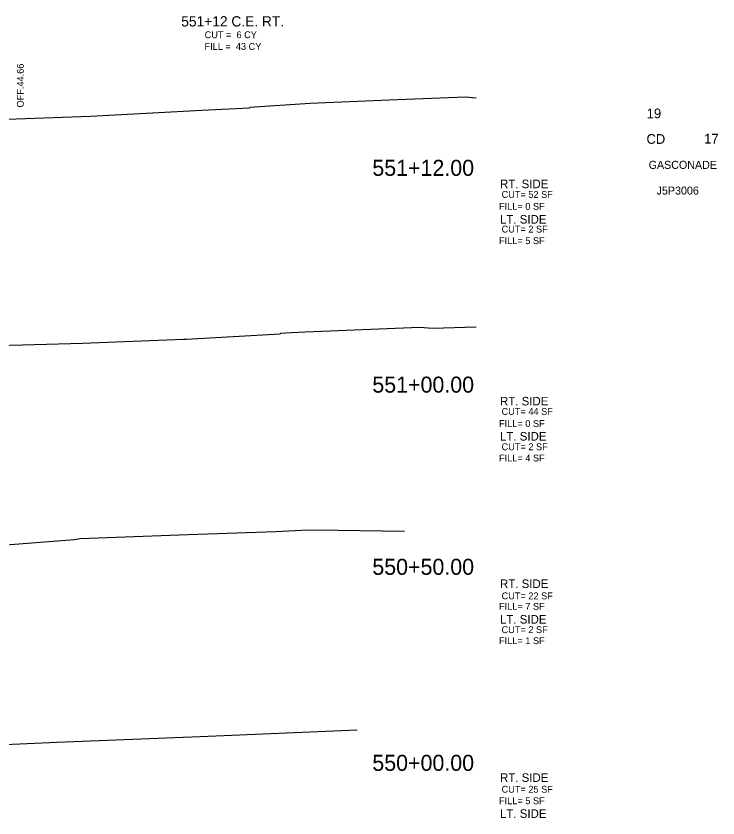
# Model space of a CAD drawing. Extents: x -4 to 359, y 0 to 1436.
# Drawn here: x 297.2 to 358.6, y 924 to 994.1 of the extents above; entities that cross this region are included whole.
import ezdxf

# ---------------------------------------------------------------- set-up
doc = ezdxf.new("R2010")
doc.units = 0
for name, color, linetype in [('Common-Title block info', 7, 'Continuous'), ('XS-Existing surface-ground', 7, 'Continuous'), ('XS-Text-earthwork labels', 7, 'Continuous'), ('XS-Text-offset label', 7, 'Continuous'), ('XS-Text-tie elevation', 7, 'Continuous')]:
    doc.layers.add(name, color=color, linetype=linetype)

msp = doc.modelspace()

# ---------------------------------------------------------------- linework, layer by layer
at = {"layer": 'XS-Existing surface-ground'}
for p, q in [((322.981, 986.503), (329.892, 986.795)), ((329.892, 986.795), (336.553, 987.062)), ((336.553, 987.062), (337.5, 986.997)), ((303.741, 985.392), (313.506, 985.892)), ((313.506, 985.892), (317.66, 986.121)), ((317.66, 986.121), (317.685, 986.159)), ((317.685, 986.159), (322.981, 986.503)), ((294.465, 985.036), (303.741, 985.392)), ((333.671, 966.846), (337.5, 966.957)), ((312.119, 965.88), (320.359, 966.334)), ((320.359, 966.334), (320.409, 966.409)), ((320.409, 966.409), (321.334, 966.469)), ((321.334, 966.469), (322.54, 966.52)), ((322.54, 966.52), (332.57, 966.922)), ((332.57, 966.922), (333.671, 966.846)), ((303.044, 965.529), (311.881, 965.868)), ((311.881, 965.868), (312.119, 965.88)), ((294.329, 965.286), (297.792, 965.395)), ((297.792, 965.395), (303.044, 965.529)), ((302.841, 948.449), (312.304, 948.81)), ((312.304, 948.81), (319.961, 949.055)), ((319.961, 949.055), (322.775, 949.213)), ((322.775, 949.213), (325.427, 949.18)), ((325.427, 949.18), (331.21, 949.102)), ((284.805, 947.033), (302.351, 948.364)), ((302.351, 948.364), (302.841, 948.449)), ((313.335, 931.153), (327.095, 931.723)), ((295.167, 930.401), (300.81, 930.64)), ((300.81, 930.64), (313.335, 931.153))]:
    msp.add_line(p, q, dxfattribs=at)

# ---------------------------------------------------------------- texts
at = {"layer": 'Common-Title block info'}
for s, height, p in [('19', 0.85, (352.417, 985.199)), ('CD', 0.85, (352.395, 982.961)), ('17', 0.85, (357.442, 982.988)), ('GASCONADE', 0.7, (352.581, 980.774)), ('J5P3006', 0.7, (353.279, 978.524))]:
    msp.add_text(s, height=height, dxfattribs=at).set_placement(p)
at = {"layer": 'XS-Text-earthwork labels'}
for s, height, p in [('551+12 C.E. RT.', 0.9, (311.692, 993.222)), ('CUT =  6 CY           ', 0.6, (313.739, 992.199)), ('FILL =  43 CY           ', 0.6, (313.729, 991.178)), ('RT. SIDE', 0.75, (339.577, 979.083)), (' CUT= 52 SF           ', 0.6, (339.495, 978.235)), ('FILL= 0 SF           ', 0.6, (339.495, 977.191)), ('LT. SIDE', 0.75, (339.577, 975.987)), (' CUT= 2 SF           ', 0.6, (339.495, 975.205)), ('FILL= 5 SF           ', 0.6, (339.495, 974.192)), ('RT. SIDE', 0.75, (339.577, 960.088)), (' CUT= 44 SF           ', 0.6, (339.495, 959.262)), ('FILL= 0 SF           ', 0.6, (339.495, 958.203)), ('LT. SIDE', 0.75, (339.577, 957.012)), (' CUT= 2 SF           ', 0.6, (339.495, 956.171)), ('FILL= 4 SF           ', 0.6, (339.495, 955.188)), ('RT. SIDE', 0.75, (339.577, 944.123)), (' CUT= 22 SF           ', 0.6, (339.495, 943.135)), ('FILL= 7 SF           ', 0.6, (339.495, 942.215)), ('LT. SIDE', 0.75, (339.577, 941.011)), (' CUT= 2 SF           ', 0.6, (339.495, 940.181)), ('FILL= 1 SF           ', 0.6, (339.495, 939.216)), ('RT. SIDE', 0.75, (339.577, 927.169)), (' CUT= 25 SF           ', 0.6, (339.495, 926.225)), ('FILL= 5 SF           ', 0.6, (339.495, 925.22)), ('LT. SIDE', 0.75, (339.577, 924.026))]:
    msp.add_text(s, height=height, dxfattribs=at).set_placement(p)
at = {"layer": 'XS-Text-offset label'}
for s, p in [('           551+12.00           ', (322.687, 980.163)), ('           551+00.00           ', (322.687, 961.205)), ('           550+50.00           ', (322.687, 945.277)), ('           550+00.00           ', (322.687, 928.137))]:
    msp.add_text(s, height=1.4, dxfattribs=at).set_placement(p)
at = {"layer": 'XS-Text-tie elevation'}
msp.add_text('OFF.44.66', height=0.6, rotation=90, dxfattribs=at).set_placement((297.913, 986.14))

doc.saveas('drawing.dxf')
